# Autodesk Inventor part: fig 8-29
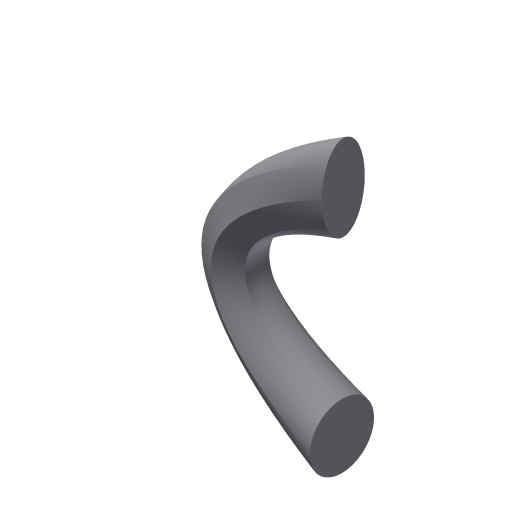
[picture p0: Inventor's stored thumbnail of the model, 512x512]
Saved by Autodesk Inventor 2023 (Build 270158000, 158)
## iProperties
Created: 2008-06
Part Number: fig 8-29
Document SubType Name: Modeling
Designer: CADCIM
Density: 1 g/cm^3
Material: Generic
Appearance: Default
Author: CADCIM
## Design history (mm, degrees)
sketch "Sketch1"
  geometry: L1 (-0.077, 5.773)-(4.961, 2.953); L2 (4.961, 2.953)-(5.038, -2.82); L3 (5.038, -2.82)-(0.077, -5.773); L4 (0.077, -5.773)-(-4.961, -2.953); L5 (-4.961, -2.953)-(-5.038, 2.82); L6 (-5.038, 2.82)-(-0.077, 5.773); 1 further point
  constraints: 12 end point, 13 other
  dimensions: "d0" = 10 distance between parallel lines of L2 L5
workplane "Work Plane1"
sketch "Sketch2"
  geometry: C1 r 7.5 at (-0.159, -25); 1 further point
  constraints: 1 centre point
  dimensions: "d2" = 15 diameter of C1; "d3" = 25 vertical distance of C1.centre point (0, 0)
sketch "Sketch3" dims "d4" = 10, "d5" = 5
  geometry: 2 further points; 1 other entity
  constraints: 2 other
  dimensions: "d6" = 25 vertical distance of point (0.175, 25) point (0, 0)
loft "Loft1" sketch "Sketch2", "Sketch3" dims "d7" = 0, "d8" = 90 deg, "d9" = 0, "d10" = 90 deg, "d11" = 0, "d12" = 90 deg
body "Solid1"
other parameters: "d1" = 25
